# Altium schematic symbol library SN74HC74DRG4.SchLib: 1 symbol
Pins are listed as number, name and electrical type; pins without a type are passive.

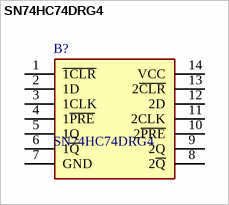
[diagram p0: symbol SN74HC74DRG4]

## SN74HC74DRG4
designator B?
Dual D-Type Positive-Edge-Triggered Flip-Flops With Clear and Preset; Manufacturer_Name: Texas Instruments; Geometry.Height: 1.75mm
footprint SOIC127P600X175-14N
pins: 1 ~{1CLR}, 2 1D, 3 1CLK, 4 1~{PRE}, 5 1Q, 6 1~{Q}, 7 GND, 8 2~{Q}, 9 2Q, 10 2~{PRE}, 11 2CLK, 12 2D, 13 2~{CLR}, 14 VCC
